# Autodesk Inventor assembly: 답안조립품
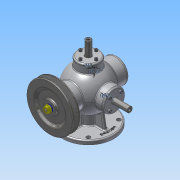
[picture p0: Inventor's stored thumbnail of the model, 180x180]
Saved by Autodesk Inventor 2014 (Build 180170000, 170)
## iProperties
Created: 2016-01
Part Number: 답안조립품
Document SubType Name: Assembly
Designer: Administrator
Author: Administrator
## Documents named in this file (17)
- C:\Users\Administrator\Desktop\360108V1009\답안조립품.iam
- C:\Users\Administrator\Desktop\360108V1009\본체.ipt
- C:\Users\Administrator\Desktop\360108V1009\본체커버.ipt
- C:\Users\Administrator\Desktop\360108V1009\베어링- 6202.ipt
- C:\Users\Administrator\Desktop\360108V1009\앞커버.ipt
- C:\Users\Administrator\Desktop\360108V1009\뒤커버.ipt
- C:\Users\Administrator\Desktop\360108V1009\슬라이드 커버.ipt
- C:\Users\Administrator\Desktop\360108V1009\축.ipt
- C:\Users\Administrator\Desktop\360108V1009\오일실.ipt
- C:\Users\Administrator\Desktop\360108V1009\키-4x4.ipt
- C:\Users\Administrator\Desktop\360108V1009\V-벨트풀리.ipt
- C:\Users\Administrator\Desktop\360108V1009\와셔 8x17.ipt
- C:\Users\Administrator\Desktop\360108V1009\너트-M8x1.ipt
- C:\Users\Administrator\Desktop\360108V1009\볼트 M4x0.7.ipt
- C:\Users\Administrator\Desktop\360108V1009\슬라이드.ipt
- C:\Users\Administrator\Desktop\360108V1009\스프링1.ipt
- C:\Users\Administrator\Desktop\360108V1009\스프링2.ipt
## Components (18 placed, 2 different names)
1. V-벨트풀리:1 — 각도:2, 플러쉬:1
2. M4x0.7x12:17
3. M4x0.7x12:4
4. M4x0.7x12:5
5. M4x0.7x12:6
6. M4x0.7x12:7
7. M4x0.7x12:3
8. M4x0.7x12:8
9. M4x0.7x12:9
10. M4x0.7x12:10
11. M4x0.7x12:1
12. M4x0.7x12:11
13. M4x0.7x12:12
14. M4x0.7x12:13
15. M4x0.7x12:2
16. M4x0.7x12:14
17. M4x0.7x12:15
18. M4x0.7x12:16
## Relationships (2: Angle 1, Flush 1)
- 각도:2 [Angle]: V-벨트풀리:1
- 플러쉬:1 [Flush]: V-벨트풀리:1
